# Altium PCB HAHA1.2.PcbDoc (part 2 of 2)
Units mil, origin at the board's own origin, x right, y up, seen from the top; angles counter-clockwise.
Board outline 7003.97 x 7003.97 mil, 2 copper layers (Top Layer, Bottom Layer); 140 components, 182 nets, 713 pads, 299 vias.
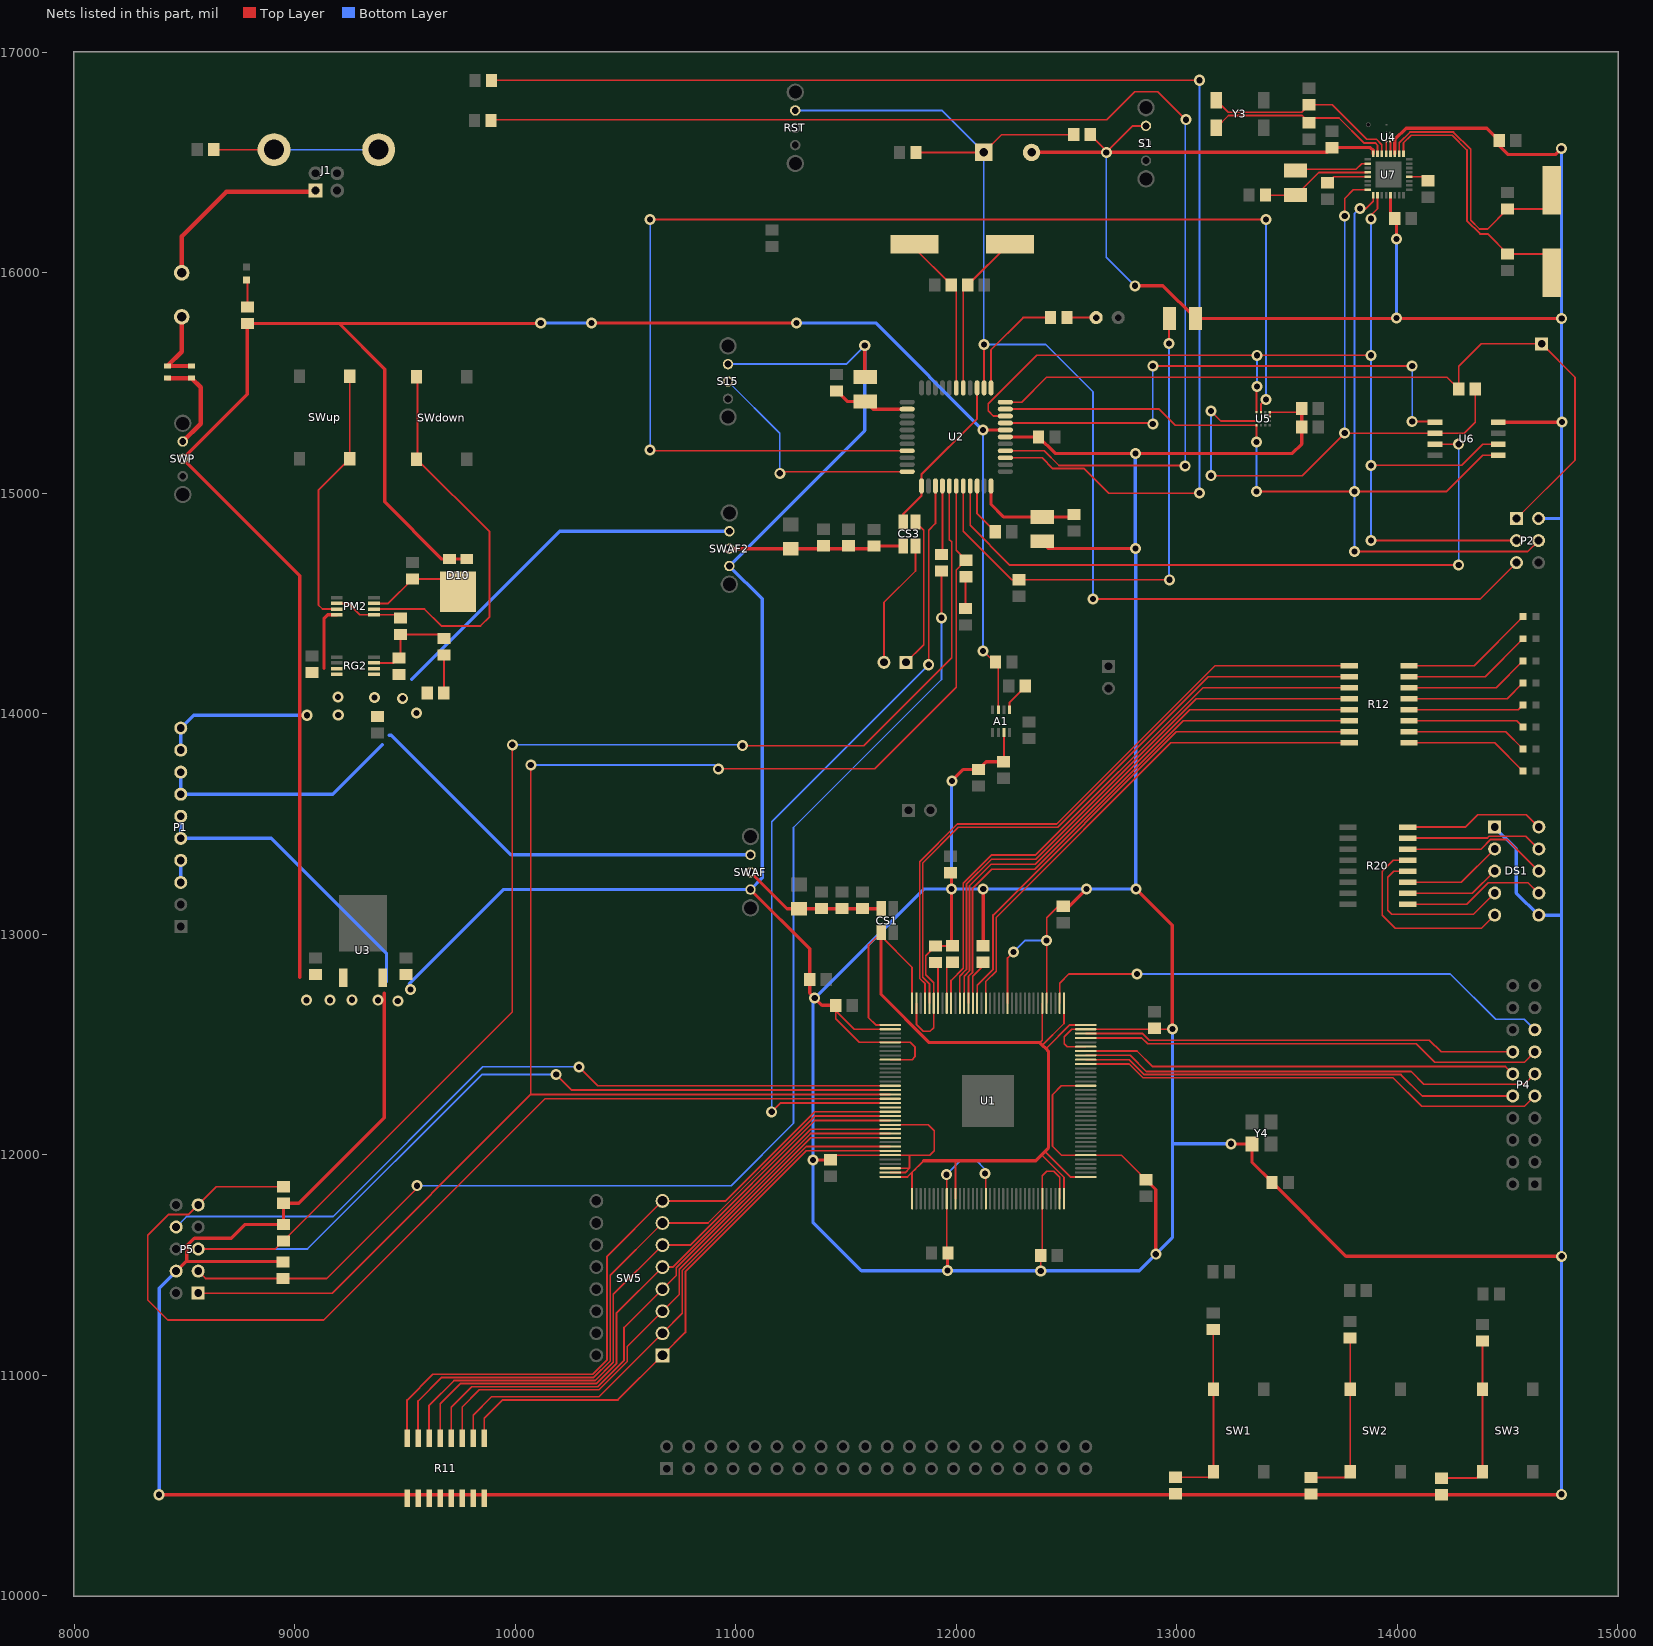
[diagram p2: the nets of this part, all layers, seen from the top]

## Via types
v1: diameter 50, hole 28, Top Layer to Bottom Layer, 295 vias
v2: diameter 236.22, hole 125.98, Top Layer to Bottom Layer, 4 vias

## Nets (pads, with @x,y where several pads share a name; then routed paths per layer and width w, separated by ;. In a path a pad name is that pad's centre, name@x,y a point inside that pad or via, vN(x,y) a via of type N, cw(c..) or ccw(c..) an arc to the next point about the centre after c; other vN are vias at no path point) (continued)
HT9: P4.9 U1.99 | length 2135.1
  Top Layer w8: U1.99@12586.83,12411.83 12784.56,12411.83 12846.4,12350 13979.8,12350 14109.8,12220 14576,12220 P4.9@14623,12267
HT10: P4.10 U1.100 | length 2004.3
  Top Layer w8: U1.100@12586.83,12431.52 12784.68,12431.52 12852.2,12364 14016,12364 14113,12267 P4.10@14523,12267
HT11: P4.11 U1.101 | length 2110
  Top Layer w8: U1.101@12586.83,12451.2 12788.8,12451.2 12862,12378 14062,12378 14120,12320 14576,12320 P4.11@14623,12367
HT12: P4.12 U1.102 | length 1979.2
  Top Layer w8: U1.102@12586.83,12470.89 12819.11,12470.89 12890,12400 14490,12400 P4.12@14523,12367
HT13: P4.13 U1.105 | length 2101.2
  Top Layer w8: U1.105@12586.83,12529.94 12841.26,12529.94 12867.2,12504 14086,12504 14170,12420 14576,12420 P4.13@14623,12467
HT14: P4.14 U1.106 | length 1970.4
  Top Layer w8: U1.106@12586.83,12549.63 12845.37,12549.63 12875,12520 14145,12520 14198,12467 P4.14@14523,12467
HT15: P4.15 U1.110 | length 2367.5
  Top Layer w8: U1.110@12468.72,12687.43 12468.72,12778.72 12510,12820 v1(12820,12820)
  Bottom Layer w8: v1(12820,12820) 14240,12820 14445,12615 14575,12615 P4.15@14623,12567
INT1: U2.30 U5.12 | length 5893.5
  Top Layer w8: v1(10611,16241) v1@13401,16241 ; v1(10612,15196) 10612,15192.02 U2.30@11777.56,15192.01 ; U5.12@13381.16,15366.53 13381.16,15402.47 v1@13404,15425.32
  Bottom Layer w8: v1(10611,16241) 10612,16240 v1(10612,15196) ; v1@13401,16241 v1@13404,16238 ; v1(13404,15425) v1@13404,16238 ; v1(13404,16241) v1@13404,16238
JTAGEN: P5.8 U1.15 | length 3616.6
  Top Layer w8: v1(10289,12399) 10374.59,12313.41 ; 10417,12313.41 10374.59,12313.41 ; U1.15@11701,12313.41 10374.59,12313.41
  Bottom Layer w8: P5.8@8463,11673 8510,11720 9174,11720 9853,12399 v1(10289,12399)
L1: R12.1 U1.141 | length 2967
  Top Layer w8: U1.141@11858.48,12687.43 11858.48,12775 11834,12799.48 11834,13329 12005,13500 12455,13500 13173,14218 R12.1@13781,14218
L2: R12.2 U1.140 | length 2931.2
  Top Layer w8: U1.140@11878.17,12687.43 11878.17,12775.11 11848,12805.28 11848,13323.2 12009.8,13485 12459.8,13485 13142.8,14168 R12.2@13781,14168
L3: R12.3 U1.135 | length 2683.5
  Top Layer w8: U1.135@11976.59,12687.43 11976.59,12790.59 12032,12846 12032,13232 12160,13360 12360.8,13360 13118.8,14118 R12.3@13781,14118
L4: R12.4 U1.133 | length 2634.9
  Top Layer w8: U1.133@12015.96,12687.43 12015.96,12810.16 12046,12840.2 12046,13226.2 12159.8,13340 12360.6,13340 13088.6,14068 R12.4@13781,14068
L5: R12.5 U1.132 | length 2594.4
  Top Layer w8: U1.132@12035.65,12687.43 12035.65,12810.05 12060,12834.4 12060,13220.4 12157.3,13317.7 12358.1,13317.7 13058.4,14018 R12.5@13781,14018
L6: R12.6 U1.131 | length 2550.7
  Top Layer w8: U1.131@12055.33,12687.43 12055.33,12809.93 12074,12828.6 12074,13209 12160,13295 12355.2,13295 13028.2,13968 R12.6@13781,13968
L7: R12.7 U1.129 | length 2387.7
  Top Layer w8: U1.129@12094.7,12687.43 12094.7,12769.7 12167,12842 12167,13087 12998,13918 R12.7@13781,13918
L8: R12.8 U1.127 | length 2336.1
  Top Layer w8: U1.127@12134.07,12687.43 12134.07,12785.94 12181,12832.87 12181,13076 12973,13868 R12.8@13781,13868
L_AD: P6.1 R19.2 U2.40 | length 2419.4
  Top Layer w8: U2.40@12031.5,15032.56 12031.5,14827.5 12252,14607 v1(12967,14607) ; v1(12964,15678) 12964,15789 P6.1@12967,15792
  Bottom Layer w8: v1(12964,15678) 12964,14610 v1(12967,14607)
MISO: R21.2 U5.3 U6.2 U7.32 | length 3149.7
  Top Layer w8: v1(13155,15079) 13568,15079 v1(13761,15272) U6.2@14170,15272 14303,15272 14352.4,15321.4 R21.2@14352.4,15472 ; v1(13155,15372) 13199.84,15327.16 U5.3@13360.96,15327.16 ; v1(13761,16257) 13761,16336 13800.59,16375.59 U7.32@13864.41,16375.59
  Bottom Layer w8: v1(13155,15079) v1(13155,15372) ; v1(13761,15272) v1(13761,16257)
MISO_I: J2.1 P2.1 R21.1 U2.11 | length 3609.4
  Top Layer w8: U2.11@12222.44,15412.48 12296.48,15412.48 12409,15525 14224.6,15525 R21.1@14277.6,15472 14277.6,15574.6 14380,15677 J2.1@14654,15677 14805,15526 14805,15150 P2.1@14540,14885
MOSI: P2.4 U2.10 U5.4 U6.5 U7.1 | length 5155.1
  Top Layer w8: U2.10@12222.44,15380.98 12920.02,15380.98 12993.53,15307.47 U5.4@13360.96,15307.47 v1(13361,15232) v1(13361,15232) ; v1(13361,15008) v1(13805,15008) 14223,15008 14387,15172 U6.5@14457.4,15172 ; v1(13805,14735) 14590,14735 P2.4@14640,14785 ; v1(13830,16291) 13858,16291 13890,16323 U7.1@13890,16350
  Bottom Layer w8: v1(13361,15008) v1(13361,15232) ; v1(13805,14735) v1(13805,15008) 13805,16266 v1(13830,16291)
NetA1_5: A1.5 C51.1 | length 136.9
  Top Layer w8: A1.5@12241.77,14017.36 12241.77,14051.77 12312.4,14122.4 C51.1@12312.4,14125
NetC4_2: C4.2 J1.5 J1.6 | length 747.6
  Top Layer w8: C4.2@8633.4,16557 8906.93,16557 J1.5@8906.99,16557.06
  Bottom Layer w8: J1.5@8906.99,16557.06 J1.6@9381.01,16557.06
NetC18_2: C18.2 R17.2 R18.2 RG2.3 | length 411.5
  Top Layer w8: RG2.3@9359.97,14230.18 9449.75,14230.18 C18.2@9479.97,14260.4 ; C18.2@9480,14260.43 R18.2@9480,14359.6 R17.2@9659.8,14359.6
NetC19_2: C19.2 D10.3 PM2.3 | length 369.8
  Top Layer w8: PM2.3@9359.97,14500.18 9424.55,14500.18 C19.2@9534.97,14610.6 D10.3@9684,14610.6
NetC20_2: C20.2 U2.16 Y1.2 | length 742.4
  Top Layer w8: U2.16@12031.5,15477.44 12031.5,15922.9 C20.2@12052.6,15944
  Top Layer w10: C20.2@12052.6,15944 12237.6,16129 Y1.2@12243.07,16129
NetC22_1: C22.1 L1.1 U2.24 | length 353.8
  Top Layer w15: C22.1@11458,15463.6 11505.72,15415.88 L1.1@11588,15415.88 11622.9,15380.98 U2.24@11777.56,15380.98
NetC23_1: C23.1 L2.1 U2.44 | length 489
  Top Layer w15: U2.44@12157.48,15032.56 12157.48,14948.52 12213.88,14892.12 L2.1@12390,14892.12 12538.72,14892.12 C23.1@12539,14892.4
NetC24_1: C24.1 U2.42 | length 241.6
  Top Layer w8: U2.42@12094.49,15032.56 12094.49,14907.11 C24.1@12176.6,14825
NetC28_2: C28.2 R5.1 | length 145.4
  Top Layer w8: C28.2@12042,14477.4 12042,14618.6 R5.1@12045,14621.6
NetC31_2: C31.2 U2.17 Y1.1 | length 741.3
  Top Layer w8: Y1.1@11810,16129 11810,16111.4 C31.2@11977.4,15944 ; U2.17@12000,15477.44 C31.2@12000,15964.4
NetC38_2: C38.2 U7.12 | length 97.9
  Top Layer w8: U7.12@14053.39,16434.65 14112.76,16434.65 C38.2@14140,16407.4
NetC39_2: C39.2 U7.17 Y2.1 | length 1211.1
  Top Layer w8: U7.17@14027.8,16538.98 14027.8,16588 14062.8,16623 14248,16623 14315,16556 14315,16235 14374.8,16175.2 14409.2,16175.2 C39.2@14500,16084.4 14665.6,16084.4 14700,16050 Y2.1@14700,16000
NetC40_2: C40.2 U7.18 Y2.2 | length 1234.7
  Top Layer w8: U7.18@14008.11,16538.98 14008.11,16588.11 14057,16637 14253.8,16637 14332,16558.8 14332,16237.8 14372,16197.8 14409.2,16197.8 C40.2@14500,16288.6 14666.6,16288.6 14700,16322 Y2.2@14700,16374.02
NetC45_1: C45.1 U7.29 | length 191.7
  Top Layer w8: C45.1@13684,16407.4 13711.24,16434.65 U7.29@13864.41,16434.65
NetCS3_1: CS3.1 PU2.1 | length 684.5
  Top Layer w8: PU2.1@11772,14233 11852,14313 11852,14832 CS3.1@11815,14869
NetCS3_2: CS3.2 PU2.2 | length 587
  Top Layer w8: PU2.2@11672,14233 11672,14504 11815,14647 CS3.2@11815,14760.73
NetD1_1: D1.1 R12.16 | length 608.8
  Top Layer w8: R12.16@14052.65,14218 14347.47,14218 D1.1@14569.47,14440
NetD2_1: D2.1 R12.15 | length 588.1
  Top Layer w8: R12.15@14052.65,14168 14397.47,14168 D2.1@14569.47,14340
NetD3_1: D3.1 R12.14 | length 567.4
  Top Layer w8: R12.14@14052.65,14118 14447.47,14118 D3.1@14569.47,14240
NetD4_1: D4.1 R12.13 | length 546.6
  Top Layer w8: R12.13@14052.65,14068 14497.47,14068 D4.1@14569.47,14140
NetD5_1: D5.1 R12.12 | length 525.9
  Top Layer w8: R12.12@14052.65,14018 14547.47,14018 D5.1@14569.47,14040
NetD6_1: D6.1 R12.11 | length 528.4
  Top Layer w8: R12.11@14052.65,13968 14541.47,13968 D6.1@14569.47,13940
NetD7_1: D7.1 R12.10 | length 549.1
  Top Layer w8: R12.10@14052.65,13918 14491.47,13918 D7.1@14569.47,13840
NetD8_1: D8.1 R12.9 | length 569.8
  Top Layer w8: R12.9@14052.65,13868 14441.47,13868 D8.1@14569.47,13740
NetD9_1: D9.1 R1.2 | length 125.1
  Top Layer w8: D9.1@8781,15967.07 8786,15962.07 R1.2@8786,15844
NetDS1_2: DS1.2 R20.11 | length 454.5
  Top Layer w8: R20.11@14047.65,13236 14290,13236 DS1.2@14440,13386
NetDS1_3: DS1.3 R20.10 | length 433.8
  Top Layer w8: R20.10@14047.65,13186 14340,13186 DS1.3@14440,13286
NetDS1_4: DS1.4 R20.12 | length 783.1
  Top Layer w8: R20.12@14047.65,13286 13984,13286 13956,13258 13956,13109 13974,13091 14345,13091 DS1.4@14440,13186
NetDS1_5: DS1.5 R20.13 | length 894.7
  Top Layer w8: R20.13@14047.65,13336 13981,13336 13931,13286 13931,13087 13991,13027 14381,13027 DS1.5@14440,13086
NetDS1_7: DS1.7 R20.9 | length 652.8
  Top Layer w8: R20.9@14047.65,13136 14314,13136 14412,13234 14592,13234 DS1.7@14640,13186
NetDS1_8: DS1.8 R20.14 | length 670.2
  Top Layer w8: R20.14@14047.65,13386 14379,13386 14423,13430 14496,13430 DS1.8@14640,13286
NetDS1_9: DS1.9 R20.15 | length 619.7
  Top Layer w8: R20.15@14047.65,13436 14407,13436 14415,13444 14582,13444 DS1.9@14640,13386
NetDS1_10: DS1.10 R20.16 | length 638.7
  Top Layer w8: R20.16@14047.65,13486 14308,13486 14364,13542 14584,13542 DS1.10@14640,13486
NetF1_1: F1.1 L3.0 L4.0 | length 359.4
  Top Layer w20: F1.1@8488,15799 8488,15641.56 L3.0@8423,15576.56 L4.0@8533,15576.56
NetL3_1: L3.1 L4.1 SWP.3 | length 447.8
  Top Layer w20: L3.1@8423,15521.44 L4.1@8533,15521.44 8574,15480.44 8574,15315.16 SWP.3@8493,15234.16
NetL6_1: L6.1 R13.2 | length 131.6
  Top Layer w8: R13.2@12502.4,15796 L6.1@12634,15796
NetP1_3: P1.3 P1.4 | length 100
  Bottom Layer w15: P1.3@8484,13235 P1.4@8484,13335
NetPM2_1: PM2.1 PM2.6 R18.1 | length 295.9
  Top Layer w8: PM2.6@9190.68,14500.18 9244.82,14500.18 9296,14449 PM2.1@9359.97,14449 R18.1@9465.4,14449
NetPM2_2: PM2.2 SWdown.1 SWdown.2 | length 1795.3
  Top Layer w8: PM2.2@9359.97,14474.59 9588.41,14474.59 9665,14398 9843,14398 9884,14439 9884,14824.82 9556.83,15151.99 SWdown.2@9556.83,15526.01
NetPM2_7: PM2.7 SWup.1 SWup.2 | length 1186.2
  Top Layer w8: PM2.7@9190.68,14474.59 9126.41,14474.59 9108,14493 9108,15013.82 SWup.2@9250.17,15155.99 SWup.1@9250.17,15530.01
NetR7_2: R7.2 U2.3 | length 6022.6
  Top Layer w8: R7.2@9899.4,16872 v1(13103,16872) ; U2.3@12222.44,15160.51 12389.01,15160.51 12438,15111.52 12580.48,15111.52 12692,15000 v1(13103,15000)
  Bottom Layer w8: v1(13103,15000) v1(13103,16872)
NetR8_2: R8.2 U2.4 | length 5671.8
  Top Layer w8: R8.2@9896.4,16693 12683,16693 12810,16820 12914,16820 v1(13041,16693) ; U2.4@12222.44,15192.01 12398.99,15192.01 12465.48,15125.52 13035.48,15125.52 v1(13038,15123)
  Bottom Layer w8: v1(13038,15123) 13038,16674 13030,16682 v1(13041,16693)
NetR9_1: R9.1 U1.138 | length 189.4
  Top Layer w8: R9.1@11905,12871.6 11917.54,12859.06 U1.138@11917.54,12687.43
NetR10_1: R10.1 U1.130 | length 205.6
  Top Layer w8: U1.130@12075.02,12687.43 12075.02,12809.82 12122,12856.8 R10.1@12122,12873.6
NetR13_1: R13.1 U2.12 | length 503.4
  Top Layer w8: U2.12@12157.48,15477.44 12157.48,15650.48 12303,15796 R13.1@12427.6,15796
NetR14_1: R14.1 U1.136 | length 159.1
  Top Layer w8: U1.136@11956.91,12687.43 11956.91,12846.5
NetR16_2: R16.2 R17.1 | length 171
  Top Layer w8: R16.2@9678,14095.63 R17.1@9678,14266.6
NetR23_2: R23.2 R24.1 SW1.1 SW1.2 | length 826.8
  Top Layer w8: R23.2@12994,10538.4 13141.24,10538.4 SW1.1@13165.83,10562.99 SW1.2@13165.83,10937.01 ; SW1.2@13165,10937.83 R24.1@13165,11208.6
NetR25_2: R25.2 R26.1 SW2.1 SW2.2 | length 794.9
  Top Layer w8: R25.2@13608,10537.4 13760.24,10537.4 SW2.1@13785.83,10562.99 SW2.2@13785.83,10937.01 ; SW2.2@13786,10937.18 R26.1@13786,11169.6
NetR27_2: R27.2 R28.1 SW3.1 SW3.2 | length 790.3
  Top Layer w8: R27.2@14200,10534.4 14357.24,10534.4 SW3.1@14385.83,10562.99 SW3.2@14385.83,10937.01 14386,10937.18 R28.1@14386,11155.6
NetU4_B1: U4.B1 U7.21 | length 56.4
  Top Layer w8: U7.21@13949.06,16538.98 13949.06,16594.06 U4.B1@13950,16595
NetU4_B2: U4.B2 U7.20 | length 57.3
  Top Layer w8: U4.B2@13965.75,16595 13968.74,16592.01 U7.20@13968.74,16538.98
PE2: S15.2 U2.33 | length 1102.3
  Top Layer w8: v1(11200,15090) 11200,15100 11202.48,15097.52 U2.33@11777.56,15097.52
  Bottom Layer w8: S15.2@10965,15506.42 11200,15271.42 v1(11200,15090)
PF6: R2.1 U2.37 | length 312.8
  Top Layer w8: R2.1@11933,14721.4 11937.01,14725.41 U2.37@11937.01,15032.56
RST: C53.2 D11.1 P2.5 R15.1 RST.3 U2.13 | length 6261.1
  Top Layer w8: C53.2@11817.4,16545 D11.1@12125,16545 12205,16625 R15.1@12532.6,16625 ; U2.13@12125.98,15477.44 v1(12126,15674) ; v1(12620,14520) 14375,14520 P2.5@14540,14685
  Bottom Layer w8: RST.3@11270,16735.16 11934.84,16735.16 D11.1@12125,16545 12125,15675 v1(12126,15674) 12406,15674 12620,15460 v1(12620,14520)
S1: R11.1 SW5.1 U1.30 | length 2594.6
  Top Layer w8: R11.1@9860,10715 9860,10805 9944,10889 10466,10889 SW5.1@10668,11091 10772,11195 10772,11470 11320.14,12018.14 U1.30@11701,12018.14
S2: R11.2 SW5.2 U1.29 | length 2614.5
  Top Layer w8: R11.2@9810,10715 9810,10820 9893,10903 10380,10903 SW5.2@10668,11191 10758,11281 10758,11475.8 11320.02,12037.82 U1.29@11701,12037.82
S3: R11.3 SW5.3 U1.27 | length 2695.4
  Top Layer w8: R11.3@9760,10715 9760,10857 9838,10935 10379.99,10935 10508,11063.01 10508,11131 SW5.3@10668,11291 10744,11367 10744,11481.6 11339.59,12077.19 U1.27@11701,12077.19
S4: R11.4 SW5.4 U1.26 | length 2752.9
  Top Layer w8: R11.4@9710,10715 9710,10856 9803,10949 10374.2,10949 10494,11068.8 10494,11217 SW5.4@10668,11391 10730,11453 10730,11487.4 11339.48,12096.88 U1.26@11701,12096.88
S5: R11.5 SW5.5 U1.25 | length 2847.3
  Top Layer w8: R11.5@9660,10715 9660,10872 9751,10963 10368.4,10963 10459,11053.6 10459,11282 SW5.5@10668,11491 10713.8,11491 11339.36,12116.56 U1.25@11701,12116.56
S6: R11.6 SW5.6 U1.23 | length 2955.9
  Top Layer w8: R11.6@9610,10715 9610,10864 9723,10977 10362.6,10977 10445,11059.4 10445,11368 SW5.6@10668,11591 10794.01,11591 11358.94,12155.93 U1.23@11701,12155.93
S7: R11.7 SW5.7 U1.22 | length 3072.8
  Top Layer w8: R11.7@9560,10715 9560,10884 9667,10991 10356.8,10991 10431,11065.2 10431,11454 SW5.7@10668,11691 10874.21,11691 11358.82,12175.61 U1.22@11701,12175.61
S8: R11.8 SW5.8 U1.21 | length 3180.2
  Top Layer w8: R11.8@9510,10715 9510,10888 9627,11005 10351,11005 10417,11071 10417,11540 SW5.8@10668,11791 10954.41,11791 11358.71,12195.3 U1.21@11701,12195.3
SCLK: P2.3 U2.9 U5.1 U6.6 U7.2 | length 5833.9
  Top Layer w8: U2.9@12222.44,15349.49 12168.51,15349.49 12145,15373 12145,15406 12364,15625 v1(13363,15625) v1(13880,15625) v1@13881,15625 ; U5.1@13360.98,15366.53 13360.98,15466.02 13359.82,15466.02 13363,15469.2 v1(13363,15483) ; v1(13880,14785) P2.3@14540,14785 ; v1(13880,16244) 13872,16244 13868,16248 13909.68,16289.68 U7.2@13909.68,16350 ; v1@13884,15126 14291,15126 14387,15222 U6.6@14457.4,15222
  Bottom Layer w8: v1(13363,15625) v1(13363,15483) v1@13364,15624.99 ; v1(13880,14785) v1(13880,15125) v1(13880,15625) v1(13880,16244) v1@13881,15625
SMPSFILT1: L5.2 U7.26 | length 339.5
  Top Layer w8: L5.2@13538,16462.12 13544.21,16468.33 13812.33,16468.33 13837.7,16493.7 U7.26@13864.41,16493.7
SMPSFILT2: C46.2 L5.1 U7.28 | length 503.6
  Top Layer w8: C46.2@13402.4,16351 L5.1@13537.12,16351 ; L5.1@13538,16351.88 13541.88,16351.88 13644.33,16454.33 U7.28@13864.41,16454.33
SS: U2.8 U6.1 | length 2464.6
  Top Layer w8: U2.8@12222.44,15317.99 12889.01,15317.99 12891,15316 v1(12891,15314) ; v1(12891,15576) v1(14067,15576) ; v1(14067,15325) 14167,15325 U6.1@14170,15322
  Bottom Layer w8: v1(12891,15314) v1(12891,15576) ; v1(14067,15325) v1(14067,15576)
SXTAL0: C1.2 U7.23 Y3.1 | length 866.6
  Top Layer w8: Y3.1@13178,16656.02 13233.98,16712 13567.8,16712 C1.2@13600,16679.8 13621.2,16701 13735,16701 13848,16588 13899,16588 13909.68,16577.31 U7.23@13909.68,16538.98
SXTAL1: C7.2 U7.22 Y3.4 | length 903.7
  Top Layer w8: Y3.4@13178,16782 13233,16727 13565.4,16727 C7.2@13599,16760.6 13704.4,16760.6 13861,16604 13905,16604 13929.37,16579.63 U7.22@13929.37,16538.98
TCK: P5.1 R5.2 U1.17 U2.39 | length 8043.3
  Top Layer w8: P5.1@8563,11373 9170,11373 10071.04,12274.04 ; v1(10071.04,13767) 10071.04,12274.04 ; v1(10921,13750) 11630,13750 12000,14120 12000,14651.4 R5.2@12045,14696.4 12000,14741.4 U2.39@12000,15032.56 ; U1.17@11701,12274.04 10071.04,12274.04
  Bottom Layer w8: v1(10071.04,13767) 10904,13767 v1(10921,13750)
TD: U1.19 U2.36 | length 3699.6
  Top Layer w8: v1(11163,12195) 11202.67,12234.67 U1.19@11701,12234.67 ; v1(11875,14222) 11875,14832 11905.51,14862.51 U2.36@11905.51,15032.56
  Bottom Layer w8: v1(11163,12195) 11163,13510 v1(11875,14222)
TDI: P5.9 R3.2 U1.18 | length 4820.6
  Top Layer w8: R3.2@8950,11855.4 8645.4,11855.4 P5.9@8563,11773 8520,11730 8429,11730 8334,11635 8334,11342 8425,11251 9132,11251 10135.35,12254.35 U1.18@11701,12254.35
TDO: P5.3 R2.2 R6.2 | length 5792.2
  Top Layer w8: P5.3@8563,11473 8596.4,11439.6 R6.2@8947,11439.6 9145.6,11439.6 9555,11849 v1(9555,11860) ; v1(11933,14435) R2.2@11933,14646.6
  Bottom Layer w8: v1(9555,11860) 10979,11860 11262,12143 11262,13484 11933,14155 v1(11933,14435)
TMS: P5.5 R4.2 U1.16 U2.38 | length 9517.1
  Top Layer w8: P5.5@8563,11573 8912.4,11573 R4.2@8949,11609.6 9987,12647.6 v1(9987,13859) ; v1(10186,12364) 10256.27,12293.73 U1.16@11701,12293.73 ; v1(11031,13855) 11580,13855 11979,14254 11979,14779 11968.5,14789.5 U2.38@11968.5,15032.56
  Bottom Layer w8: P5.5@8563,11573 9058,11573 9849,12364 v1(10186,12364) ; v1(9987,13859) 11027,13859 v1(11031,13855)
V133: CS1.1 U1.1 U1.36 U1.37 U1.47 U1.72 U1.73 U1.108 U1.109 U1.114 U1.144 | length 4661.2
  Top Layer w8: U1.36@11701,11900.02 11779.02,11900.02 11799.43,11920.43 ; U1.1@11701,12589 11635,12589 11602,12622 11602,12951 CS1.1@11659,13008 11659,12991 11799.43,12850.57 U1.144@11799.43,12687.43 ; U1.37@11799.43,11801.6 11799.43,11920.43 ; 11816,11937 11799.43,11920.43 ; 11852,11973 11799.43,11920.43 ; U1.47@11996.28,11801.6 11996.28,11971.72 ; 12379,12509 12389.98,12519.98 U1.114@12389.98,12687.43 ; 12387.5,11999.5 12488.4,11898.6 U1.72@12488.4,11801.6 ; 12390.5,12497.5 12488.4,12595.4 U1.109@12488.4,12687.43 ; 12403.5,12013.5 12516.98,11900.02 U1.73@12586.83,11900.02 ; 12407,12481 12515,12589 U1.108@12586.83,12589
  Top Layer w15: CS1.1@11659,12991 11659,12727 11877,12509 12379,12509 12390.5,12497.5 12407,12481 12418,12470 12418,12031 12360,11973 12075,11973 11852,11973
V233: CS3.3 U2.14 U2.34 | length 747
  Top Layer w10: CS3.3@11759.88,14869 11759.88,14905.88 11842.52,14988.52 U2.34@11842.52,15032.56 11842.52,15085.52 12094.49,15337.49 U2.14@12094.49,15477.44
VCC_3.3A: C15.2 C18.1 P1.7 P1.8 R16.1 RG2.1 RG2.2 SWAF2.3 SWAF.3 | length 4689.1
  Bottom Layer w15: P1.8@8484,13735 P1.7@8484,13635 9173,13635 9398,13860 ; 9428,13903 9438,13903 9980.84,13360.16 SWAF.3@11067,13360.16 ; 9531,14156 10202.16,14827.16 SWAF2.3@10971,14827.16
  other v1: 9552,14003 9490,14070 9362,14074
VCC_3.3AF: C14.2 C16.2 C33.2 C34.2 CS1.2 SWAF.2 | length 660.7
  Top Layer w15: SWAF.2@11067,13281.42 11232.54,13115.88 C16.2@11287,13115.88 11658.61,13115.88 CS1.2@11659,13116.27
VCC_3.3AF2: C10.2 C11.2 C35.2 C36.2 CS3.4 SWAF2.2 | length 775.7
  Top Layer w15: SWAF2.2@10971,14748.42 C10.2@11248.46,14748.42 ; C10.2@11249,14747.88 C11.2@11613.28,14747.88 ; C11.2@11626,14760.6 11626.13,14760.73 CS3.4@11759.88,14760.73
VCC_3.3F: A1.3 C2.2 C5.2 C6.2 C8.2 C9.2 C12.2 C13.2 C21.2 C25.2 C26.2 C27.2 C29.2 C30.2 C32.2 C37.2 C41.2 C42.1 C48.1 C49.1 D11.2 DS1.1 DS1.6 L1.2 L2.2 P1.5 P1.6 P2.2 P5.4 P6.0 R3.1 R4.1 R6.1 R9.2 R10.2 R11.9 R11.10 R11.11 R11.12 R11.13 R11.14 R11.15 R11.16 R14.2 R15.2 R23.1 R25.1 R27.1 S1.3 S15.3 SWAF2.1 SWAF.1 U1.2 U1.5 U1.9 U1.24 U1.31 U1.34 U1.35 U1.45 U1.54 U1.67 U1.71 U1.78 U1.94 U1.103 U1.107 U1.113 U1.122 U1.139 U1.143 U2.6 U3.3 U5.9 U5.10 U6.8 U7.5 U7.19 U7.24 Y4.4 | length 51042
  Top Layer w8: C5.2@11430,11977.4 11451.05,11998.45 U1.31@11701,11998.45 11880.45,11998.45 11900,12018 11900,12109 11872.75,12136.25 U1.24@11701,12136.25 ; C6.2@11453.6,12678 C6.2@11453.6,12653.4 ; U1.35@11701,11919.71 11768.26,11919.71 11787.94,11939.4 ; U1.34@11701,11939.4 11787.94,11939.4 ; U1.9@11701,12431.52 11799.52,12431.52 11812.5,12444.5 11812.5,12489.5 11791.74,12510.26 U1.5@11701,12510.26 11559.74,12510.26 11453.6,12616.4 C6.2@11453.6,12653.4 ; U1.2@11701,12569.32 11537.68,12569.32 C6.2@11453.6,12653.4 ; 11787.94,11998.45 11787.94,11939.4 ; U1.143@11819.11,12687.43 11819.11,12591.64 11850.75,12560 11881,12560 11898,12577 11898,12687.28 U1.139@11897.85,12687.43 11897.85,12781.15 11862,12817 11862,12903.4 R9.2@11905,12946.4 11906,12947.4 R14.2@11983,12947.4 ; v1(11955,11910) 11956.91,11908.09 U1.45@11956.91,11801.6 C27.2@11956.91,11560.5 ; v1(12130,11915) 12134.07,11910.93 U1.54@12134.07,11801.6 ; C49.1@12216.18,13783.58 A1.3@12216.18,13915 ; U1.122@12232,12686.93 U1.122@12232.5,12687.43 12232.5,12892.5 v1(12260,12920) ; v1(12383,11474) 12382.6,11474.4 12382.6,11529 12389.98,11536.38 U1.67@12389.98,11801.6 12389.98,11905.98 12410,11926 12441.2,11926 12468.72,11898.49 U1.71@12468.72,11801.6 ; U1.113@12409.66,12687.43 v1(12409.66,12972.26) 12409.66,13074.66 12462.4,13127.4 C30.2@12485,13127.4 ; U1.94@12586.83,12313.41 12476.41,12313.41 12436,12273 12436,12039.38 12476.93,11998.45 U1.78@12586.83,11998.45 12748.95,11998.45 C12.2@12860,11887.4 ; U1.103@12586.83,12490.58 12503.42,12490.58 12490,12504 12490,12535 12524.32,12569.32 U1.107@12586.83,12569.32 v1@12979.32,12569.32 ; R15.2@12607.4,16625 12680,16552.4 v1(12680,16545) 12800.16,16665.16 S1.3@12860,16665.16 ; U5.9@13421.04,15346.84 U5.10@13421.04,15366.53 C25.2@13550.13,15366.53
  Top Layer w15: v1(8386,10459) 14742,10459 v1(14744,10461) ; P5.4@8463,11473 8506.03,11516.03 ; R6.1@8947,11514.4 8947,11516.03 8506.03,11516.03 ; 9407,12732 9407,12168 9019.6,11780.6 R3.1@8950,11780.6 8950,11685.4 R4.1@8949,11684.4 8775.4,11684.4 8713,11622 8546,11622 8511,11587 8511,11521 8506.03,11516.03 ; SWAF.1@11067,13202.68 11335.6,12934.08 C9.2@11335.6,12795 11335.6,12733.4 v1(11358,12711) 11391,12678 C6.2@11453.6,12678 ; v1(11350,11977) C5.2@11429.6,11977 ; v1(11585,15669) 11585,15533.12 11583,15531.12 L1.2@11588,15526.12 ; v1(11960,11475) C27.2@11960,11552.6 ; R14.2@11978,12952.4 v1(11978,13205) C13.2@11978,13274.6 ; v1(11980,13695) 12032.4,13747.4 C48.1@12100,13747.4 12135,13782.4 C49.1@12215,13782.4 C49.1@12216.18,13783.58 ; R10.2@12122,12948.4 v1(12122,13205) ; U2.6@12222.44,15255 C21.2@12372.6,15255 12447.6,15180 v1(12812,15180) 13524,15180 13566.6,15222.6 C26.2@13566.6,15299 C25.2@13566.6,15383 ; D11.2@12341.54,16545 v1(12680,16545) 13682.4,16545 C42.1@13704,16566.6 13704.4,16567 13877,16567 13890,16554 U7.24@13890,16538.98 ; L2.2@12390,14778.51 12419.51,14749 v1(12812,14749) ; C30.2@12485,13127.4 12512.4,13127.4 v1(12590,13205) ; v1(12810,15940) 12937.11,15940 P6.0@13085.11,15792 v1(14745,15792) ; v1(12815,13205) 12979.32,13040.68 v1@12979.32,12569.32 ; C12.2@12860,11887.4 12904.5,11842.9 v1(12904.5,11549.5) ; v1(13245,12050) 13246,12049 Y4.4@13340.69,12049 13340.69,11965.91 C29.2@13431.6,11875 13766.6,11540 v1(14745,11540) ; C37.2@13968.74,16234.14 U7.5@13968.74,16350 ; C37.2@13984.6,16245 13996,16233.6 v1(13996,16152) ; U7.19@13988.42,16538.98 13988.42,16603.42 14040,16655 14404.6,16655 C41.2@14461.6,16598 14461.6,16575.4 14502,16535 14715,16535 v1(14743,16563) ; U6.8@14457.4,15322 v1(14746,15322)
  Bottom Layer w8: S15.3@10965,15585.16 11501.16,15585.16 v1(11585,15669) ; v1(11955,11910) 12020,11975 12090,11975 12130,11935 v1(12130,11915) ; v1(12260,12920) 12312.26,12972.26 v1(12409.66,12972.26) ; v1(12680,16545) 12680,16070 v1(12810,15940)
  Bottom Layer w15: v1(8386,10459) 8386,11396 P5.4@8463,11473 ; P1.6@8484,13535 P1.5@8484,13435 8894,13435 9417,12912 9417,12784 ; 9519,12775 9946.68,13202.68 SWAF.1@11067,13202.68 11119.87,13255.55 11119.87,14520.81 SWAF2.1@10971,14669.68 11585,15283.68 v1(11585,15669) ; v1@11978,13698 v1(11978,13205) ; v1(12812,15180) v1(12812,14749) 12813,14748 v1@12813,13208 ; v1(12815,13205) v1(12590,13205) v1(12122,13205) v1(11978,13205) ; v1(12980,12570) 12980,12050 ; v1(13245,12050) 12980,12050 ; v1(13996,15794) v1@13996,16130.2 ; DS1.1@14440,13486 14539,13387 14539,13187 14640,13086 14744,13086 ; P2.2@14640,14885 14744,14885 ; v1(14743,16563) 14744,16562 v1@14744,15792 ; v1(14744,10461) 14744,13086 ; v1(14745,15792) v1@14744,15792 ; v1(11978,13205) 11852,13205 v1(11358,12711) 11350,12703 v1(11350,11977) 11350,11695 11570,11475 v1(11960,11475) 12830,11475 v1(12904.5,11549.5) 12980,11625 12980,12050 ; 14744,13086 14744,14885 ; 14744,14885 v1@14744,15792
  other v1: 9468,12698 9378,12701 9525,12749
VCC_5V: A1.7 C3.2 C17.1 C50.2 D10.1 D10.2 P1.9 P1.10 PM2.8 R1.1 RG2.7 RG2.8 SWP.2 U2.7 U3.1 | length 10637.6
  Top Layer w8: v1(12121,14285) 12190.59,14215.41 A1.7@12190.59,14017.36
  Top Layer w15: 9023,12804 9023,13993 ; v1(9057,13993) 9023,13993 ; 9133,14205 9133,14431 9151,14449 PM2.8@9190.68,14449 ; D10.2@9779.75,14701.27 D10.1@9702.19,14701.27 9667.73,14701.27 9409,14960 9409,15562 9201.8,15769.2 ; v1(10116,15771) 10114.2,15769.2 9201.8,15769.2 ; v1(10346,15771.5) 11274.5,15771.5 v1(11275,15772) ; v1(12121,15286) 12121.5,15286.5 U2.7@12222.44,15286.5 ; 9023,13993 9023,14625.42 SWP.2@8493,15155.42 8786,15448.42 R1.1@8786,15769.2 9201.8,15769.2
  Bottom Layer w8: v1(12121,14285) v1(12121,15286)
  Bottom Layer w15: P1.9@8484,13835 P1.10@8484,13935 8542,13993 v1(9057,13993) ; v1(10116,15771) 10116.5,15771.5 v1(10346,15771.5) ; v1@11275,15771.5 11635.5,15771.5 v1(12121,15286)
  other v1: 9054,12701 9160,12701 9260,12703 9198,13994 9197,14076
VUSB: F1.2 J1.1 | length 857.8
  Top Layer w20: F1.2@8488,15999 8488,16164 8691,16367 9090.16,16367 J1.1@9094.79,16371.63
W\P\: U2.41 U6.3 | length 3124.1
  Top Layer w8: U2.41@12062.99,15032.56 12062.99,14854.01 12243,14674 v1(14278,14674) ; U6.3@14170,15222 v1(14278,15222)
  Bottom Layer w8: v1(14278,14674) v1(14278,15222)
WAIT: U1.20
pads on no net: P4.16 P5.6 P5.7 RG2.4 RST. S1. S15. SWAF2. SWAF. SWP. U1.124 U1.125 U1.128 U1.134 U2.2 U5.11 U7.4 U7.13 U7.14 U7.15 U7.16 Y3.2 Y3.3 Y4.1

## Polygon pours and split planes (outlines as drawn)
VCC_5V on Bottom Layer "5" (solid, pour order 18): 9014.97,14214 ccw(c9014.97,14179) 8979.97,14179 8979.97,14164 8979.97,13929 ccw(c9029.97,13929) 9029.97,13879 9229.97,13879 ccw(c9229.97,13904) 9254.97,13904 9254.97,14189 ccw(c9229.97,14189) 9229.97,14214
VCC_3.3A on Bottom Layer "5" (solid, pour order 16): 9304.97,14144 9304.97,14159 cw(c9359.97,14159) 9359.97,14214 9599.97,14214 cw(c9599.97,14184) 9629.97,14184 9629.97,13864 cw(c9594.97,13864) 9594.97,13829 9334.97,13829 cw(c9334.97,13859) 9304.97,13859
VCC_3.3F on Bottom Layer "5" (solid, pour order 14): 9345,12800 9345,12815 cw(c9385,12815) 9385,12855 9640,12855 cw(c9640,12835) 9660,12835 9660,12560 cw(c9635,12560) 9635,12535 9400,12535 cw(c9400,12590) 9345,12590
VCC_5V on Bottom Layer "5" (solid, pour order 8): 9255,12880 9265,12880 cw(c9265,12825) 9320,12825 9320,12605 cw(c9250,12605) 9250,12535 8935,12535 cw(c8935,12585) 8885,12585 8885,12830 cw(c8935,12830) 8935,12880
GND on Bottom Layer "b" (solid, remove dead copper, pour order 56): 13790,17080 13790,16680 15245,16680 15815,16110 16025,15900 16025,8860 7395,8860 7060,9195 5975,10280 5975,16795 5975,18270 6440,18735 6520,18655 10925,18655 13645,18655 13810,18490
VCC_5V on Top Layer "5" (solid, remove dead copper, pour order 4): 9229.97,14214 9234.97,14214 cw(c9234.97,14194) 9254.97,14194 9254.97,13969 cw(c9239.97,13969) 9239.97,13954 9004.97,13954 cw(c9004.97,13979) 8979.97,13979 8979.97,14184 cw(c9009.97,14184) 9009.97,14214
VCC_3.3A on Top Layer "5" (solid, pour order 10): 9324.97,14159 9324.97,14194 cw(c9344.97,14194) 9344.97,14214 9484.97,14214 cw(c9484.97,14179) 9519.97,14179 9519.97,14169 ccw(c9539.97,14169) 9539.97,14149 9614.97,14149 cw(c9614.97,14134) 9629.97,14134 9629.97,13979 cw(c9609.97,13979) 9609.97,13959 9349.97,13959 cw(c9349.97,13984) 9324.97,13984
VCC_3.3F on Top Layer "5" (solid, pour order 12): 9345,12795 9345,12825 cw(c9365,12825) 9365,12845 9535,12845 cw(c9535,12825) 9555,12825 9555,12675 cw(c9545,12675) 9545,12665 9365,12665 cw(c9365,12685) 9345,12685
VCC_5V on Top Layer "5" (solid, remove dead copper, pour order 2): 9280,12845 9295,12845 cw(c9295,12835) 9305,12835 9305,12685 cw(c9280,12685) 9280,12660 9030,12660 cw(c9030,12685) 9005,12685 9005,12825 9005,12830 cw(c9020,12830) 9020,12845
GND on Top Layer "t" (solid, remove dead copper, pour order 58): 13790,17130 13790,16680 16585,16680 17355,15910 17215,15770 17215,8195 6910,8195 6785,8070 6230,8625 6230,17895 13115,17895 13600,18380

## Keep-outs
Keep-Out Layer:
  lines w3.94: 8000,10000 8000,17000 15000,17000 15000,10000 8000,10000

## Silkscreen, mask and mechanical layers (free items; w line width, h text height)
Top Overlay:
  text "RST" at 12785,16840 h45
  text "D-" at 10475,16800 h50
  text "D+" at 10475,16620 h50
  text "SCLK" at 12380,15645 h50
  text "APP" at 10700,15615 h45
  text "MISO" at 12665,15505 h50
  text "TEST" at 10690,15395 h45
  text "MOSI" at 12525,15365 h50
  text "ON" at 8613,15269 h60
  text "A" at 10800,14854 h60
  text "PC7" at 10435,14825 h50 r90
  text "PORTD" at 10155,14795 h50 r90
  text "ADC1" at 12715,14585 h50
  text "F" at 10811,14583 h60
  text "AMP_OUT" at 12545,14310 h45
  text "+" at 11655,14095 h60
  text "ADC_OUT" at 12540,13985 h45
  text "14 / 13 / 12 / 11 / 8 / 10 / 7 / 6" at 10540,13950 h45 r90
  text "5V" at 8293,13844 h60
  text "141 / 140 / 135 / 133 / 132 / 131 / 129 / 127" at 13325,13730 h45
  text "3.3A" at 8184,13664 h60
  text "+" at 11765,13645 h60
  text "3.3F" at 8190,13465 h60
  text "A" at 10874,13383 h60
  text "OPEN" at 8176,13252 h60
  text "F" at 10883,13127 h60
  text "GND" at 8241,13062 h60
  text "126 / 123 / 120 / 119 / 118 / 117 / 116 / 111" at 13325,13020 h45
  text "TMS" at 9945,12955 h60 r90
  text "GND" at 14290,12740 h50
  text "GND" at 14710,12740 h50
  text "GND" at 14290,12645 h50
  text "GND" at 14710,12640 h50
  text "PIN28" at 10570,12605 h45
  text "OPEN" at 14255,12545 h50
  text "110" at 14720,12545 h50
  text "105" at 14720,12445 h50
  text "106" at 14300,12440 h50
  text "TCK" at 10020,12350 h60 r90
  text "101" at 14725,12345 h50
  text "102" at 14300,12340 h50
  text "100" at 14300,12245 h50
  text "99" at 14725,12245 h50
  text "TDI" at 10315,12150 h60
  text "98" at 14340,12145 h50
  text "97" at 14725,12145 h50
  text "PIN88" at 13070,12130 h45
  text "96" at 14340,12045 h50
  text "93" at 14720,12045 h50
  text "91" at 14725,11945 h50
  text "92" at 14340,11940 h50
  text "TDO" at 9445,11915 h60
  text "89" at 14715,11845 h50
  text "90" at 14340,11835 h50
  text "LOW" at 10085,11325 h60 r90
  text "HIGH" at 10910,11301 h60 r90
  text "33" at 10870,11135 h50 r90
  text "21 / 22 / 23 / 25 / 26 / 27 / 29 / 30" at 10155,11055 h60
  text "83" at 12510,10770 h50 r90
  text "GND" at 12615,10770 h50 r90
  text "GND" at 10710,10765 h50 r90
  text "40" at 11010,10765 h50 r90
  text "62" at 11810,10765 h50 r90
  text "57" at 11620,10760 h50 r90
  text "60" at 11715,10760 h50 r90
  text "64" at 11910,10760 h50 r90
  text "70" at 12115,10760 h50 r90
  text "75" at 12215,10760 h50 r90
  text "77" at 12315,10760 h50 r90
  text "81" at 12410,10760 h50 r90
  text "33" at 10810,10755 h50 r90
  text "38" at 10910,10755 h50 r90
  text "42" at 11115,10755 h50 r90
  text "44" at 11215,10755 h50 r90
  text "49" at 11315,10755 h50 r90
  text "51" at 11415,10755 h50 r90
  text "53" at 11515,10755 h50 r90
  text "66" at 12005,10755 h50 r90
  text "86" at 13870,10515 h45
  text "87" at 14470,10515 h45
  text "85" at 13245,10510 h45
  text "74" at 12120,10420 h50 r90
  text "76" at 12215,10420 h50 r90
  text "84" at 12520,10420 h50 r90
  text "52" at 11420,10415 h50 r90
  text "55" at 11515,10415 h50 r90
  text "58" at 11615,10415 h50 r90
  text "61" at 11715,10415 h50 r90
  text "63" at 11815,10415 h50 r90
  text "65" at 11920,10415 h50 r90
  text "69" at 12015,10415 h50 r90
  text "80" at 12320,10415 h50 r90
  text "82" at 12415,10415 h50 r90
  text "32" at 10815,10410 h50 r90
  text "39" at 10915,10410 h50 r90
  text "41" at 11015,10410 h50 r90
  text "43" at 11115,10410 h50 r90
  text "46" at 11220,10410 h50 r90
  text "50" at 11315,10410 h50 r90
  text "GND" at 12615,10360 h50 r90
  text "GND" at 10710,10355 h50 r90
  text "GND x4" at 8427,10221 h60
  text "HAHA V1.2" at 13666,10217 h60
Mechanical 1:
  lines w6: 7985,9985 15015,9985 15015,17015 7985,17015 7985,9985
